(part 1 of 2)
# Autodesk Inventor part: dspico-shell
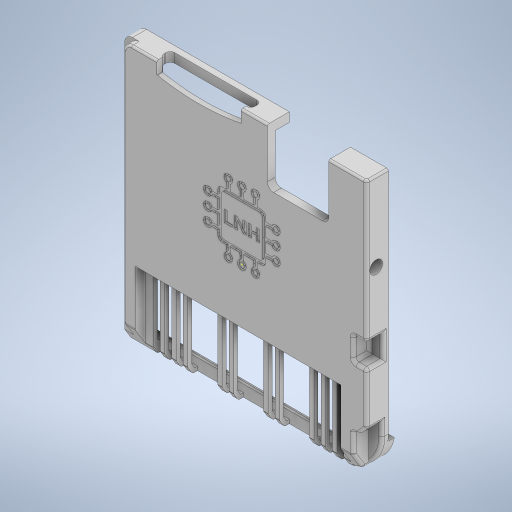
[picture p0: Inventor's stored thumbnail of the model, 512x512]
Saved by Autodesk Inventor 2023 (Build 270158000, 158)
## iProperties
RuleStatus: InUse
Created: 2023-10
Material: Genérico
Document SubType Name: Modeling
Density: 1 g/cm^3
Appearance: Valor por defecto
Author: RCuevas/Nitehack
Title: dspico-shell
Revision Number: v1.4
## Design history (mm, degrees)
sketch "Boceto1"
  geometry: L1 (16.3, -17.5)-(-16.3, -17.5); L2 (-16.3, -17.5)-(-16.3, 17.5); L3 (-16.3, 17.5)-(16.3, 17.5); L4 (16.3, 17.5)-(16.3, -17.5); L5 (16.3, -17.5)-(-16.3, 17.5); L6 (-16.3, -17.5)-(16.3, 17.5); 1 further point
  constraints: 12 end point, 2 midpoint, 2 parallel, 1 horizontal, 1 perpendicular
  dimensions: "d0" = 32.6 distance of L2.end L3.end; "d1" = 35 distance of L1.end L2.end
extrude "Extrusión1" new body sketch "Boceto1" stored distance "d2" = 3.85; taper "d3" = 0 deg
sketch "Boceto2"
  geometry: L1 (0, 35)-(3.85, 35) reference; L2 (0, 0)-(0, 35) reference; L3 (3.85, 0)-(0, 0) reference; L4 (3.85, 35)-(3.85, 0) reference; L5 (2.85, 0)-(2.85, 35); L6 (0, 35)-(0, 0) reference; L7 (0, 13.7)-(1.95, 13.7); L8 (1.95, 13.7)-(1.95, 16.7); L9 (1.95, 16.7)-(0, 16.7); L10 (2.85, 5)-(3.85, 5); L11 (3.85, 0)-(3.85, 35) reference; L12 (2.85, 5)-(2.85, 35); L13 (3.85, 35)-(0, 35) reference; L14 (2.85, 35)-(3.85, 35); 1 further point
  constraints: 14 end point, 6 point on line, 4 perpendicular, 1 collinear, 1 vertical
  dimensions: "d4" = 2.85 distance between parallel lines of L2 L5; "d5" = 3 distance of L7.end L8.end; "d6" = 1.95 distance of L7.start L7.end; "d7" = 18.3 distance between parallel lines of L1 L9; "d8" = 5 distance between parallel lines of L3 L10
extrude "Extrusión2" cut sketch "Boceto2" extent not by distance; stored distance "d9" = 0; taper "d10" = 0 deg
sketch "Boceto3"
  geometry: L1 (16.3, 17.5)-(-16.3, 17.5) reference; L2 (-16.3, 17.5)-(-16.3, -17.5) reference; L3 (-16.3, -17.5)-(16.3, -17.5) reference; L4 (16.3, -0.8)-(14.54, -0.8); L5 (14.54, -0.8)-(14.54, -3.8); L6 (14.54, -3.8)-(16.3, -3.8); L7 (16.3, -17.5)-(-16.3, -17.5) reference; L8 (14.54, -17.5)-(14.54, -11.4); L9 (14.54, -11.4)-(15.54, -11.4); L10 (15.54, -11.4)-(16.3, -10.5); L11 (-15.4, 17.5)-(-15.4, -17.5); 7 further points; 1 other entity
  constraints: 14 end point, 5 perpendicular, 3 point on line, 1 horizontal, 2 other
  dimensions: "d11" = 1.76 distance of L5.end L6.end; "d12" = 6.1 distance of L8.start L8.end; "d13" = 1.76 dimension on L8; "d14" = 1 distance of L8.end L9.end; "d15" = 7 distance from line of L3 L10.end; "d16" = 0.9 distance between parallel lines of L2 L11
  node "Contorno proyectado2"
extrude "Extrusión3" cut sketch "Boceto3" distance "d17" = 1; taper "d18" = 0 deg
extrude "Extrusión4" cut sketch "Boceto3" distance "d19" = 2.15; taper "d20" = 0 deg
extrude "Extrusión5" cut sketch "Boceto3" distance "d21" = 2; taper "d22" = 0 deg
fillet "Empalme1" dims "d23" = 5
sketch "Boceto5"
  geometry: L1 (-14.4, 1.925)-(-17.5, 0.025); L2 (-16.308, 1.925)-(-17.5, 1.925) reference; L3 (-17.5, 1.925)-(-17.5, -1.925) reference; L4 (-17.5, -1.925)-(-12.5, -1.925) reference; L5 (-12.5, -1.925)-(-12.5, -0.925) reference; L6 (-12.5, -0.925)-(-12.5, -0.075) reference; L7 (-12.5, -0.075)-(-16.308, -0.075) reference; L8 (-16.308, -0.075)-(-16.308, 1.925) reference; L9 (-16.308, -0.075)-(-16.308, 1.925) reference; L10 (-16.308, -0.075)-(-11.4, -0.075) reference; L11 (-11.4, 1.925)-(-11.4, -0.075) reference; L12 (-16.308, 1.925)-(-11.4, 1.925) reference; 2 further points
  constraints: 2 end point, 2 point on line, 1 other
  dimensions: "d24" = 3 distance from line of L1.start L11
extrude "Extrusión6" cut sketch "Boceto5" extent not by distance; stored distance "d25" = 0; taper "d26" = 0 deg
fillet "Empalme2" dims "d27" = 0.4
sketch "Boceto6"
  geometry: L1 (-13.9, -20)-(-13.9, -7.2); L2 (-13.9, -7.2)-(12.946, -7.2); L3 (12.946, -7.2)-(12.946, -19.174); L4 (11.3, -17.309)-(-16.3, -17.309) reference; L5 (0, 0)-(0, -20.377); L6 (-16.3, -17.5)-(11.3, -17.5) reference; L7 (16.3, -10.354)-(16.3, -4.2) reference; L8 (-16.3, -16.032)-(-16.3, 17.5) reference; A1 r 5 centre (11.3, -12.5) between (11.3, -17.5) and (14.387, -16.433) reference; 2 further points
  constraints: 8 end point, 2 perpendicular, 2 vertical
  dimensions: "d28" = 10.3 distance between parallel lines of L2 L6; "d29" = 3.354 distance between parallel lines of L3 L7; "d63" = 2.4 distance between parallel lines of L8 L1; "d64" = 26.846 distance of L1.end L2.end (derived)
extrude "Extrusión7" cut sketch "Boceto6" distance "d32" = 1.3; taper "d33" = 0 deg
sketch "Boceto7"
  geometry: L1 (12.946, -16.521)-(-13.9, -16.521) reference; L2 (12.946, -7.2)-(12.946, -16.521) reference; L3 (-13.9, -7.2)-(12.946, -7.2) reference; L4 (-13.9, -16.521)-(-13.9, -7.2) reference; L5 (12.946, -14.496)-(12.946, -16.521) reference; L6 (12.946, -16.521)-(-13.9, -16.521) reference; L7 (-13.9, -16.521)-(-13.9, -14.496) reference; L8 (-15.4, -14.496)-(-13.9, -14.496) reference; L9 (-16.3, -16.032)-(-15.4, -16.032) reference; L10 (11.3, -17.309)-(-16.3, -17.309) reference; L11 (14.14, -14.496)-(14.14, -16.328) reference; L12 (12.946, -14.496)-(14.14, -14.496) reference; L13 (-16.3, -17.5)-(11.3, -17.5) reference; L14 (11.3, -17.309)-(11.3, -17.5) reference; L15 (11.3, -17.309)-(-16.3, -17.309) reference; L16 (-13.9, -16.521)-(-13.9, -17.5); L17 (12.946, -16.521)-(12.946, -17.221); L18 (-16.3, -17.309)-(-16.3, -17.5) reference; L19 (-15.4, -16.032)-(-15.4, -14.496) reference; L20 (-16.3, -17.309)-(-16.3, -16.032) reference; A1 r 4.6 centre (11.3, -12.709) between (11.3, -17.309) and (14.14, -16.328) reference; A2 r 5 centre (11.3, -12.5) between (11.3, -17.5) and (14.387, -16.433) reference; A3 r 5 centre (11.3, -12.5) between (11.3, -17.5) and (16.3, -12.5) reference; A4 r 5 centre (11.3, -12.5) between (14.387, -16.433) and (16.3, -12.5) reference; 9 further points
  constraints: 4 end point, 2 point on line, 1 parallel, 1 point on circle
extrude "Extrusión8" cut sketch "Boceto7" distance "d34" = 1.25; taper "d35" = 0 deg
sketch "Boceto12"
  geometry: 1 further point
sketch "Boceto13"
  geometry: L1 (12.946, -7.2)-(12.946, -17.221) reference; L2 (-13.9, -7.2)-(12.946, -7.2) reference; L3 (-13.9, -17.5)-(-13.9, -7.2) reference; L4 (11.3, -17.5)-(-13.9, -17.5) reference; L5 (12.046, -17.5)-(12.046, -8.2); L6 (12.046, -8.2)-(-12.854, -8.2); L7 (-12.854, -8.2)-(-12.854, -17.5); L8 (-13.9, -14.287)-(-13.9, -14.496) reference; L9 (19, -16)-(-21.001, -16); A1 r 5 centre (11.3, -12.5) between (11.3, -17.5) and (12.946, -17.221) reference; 3 further points
  constraints: 8 end point, 3 perpendicular, 2 point on line, 1 midpoint, 1 vertical
  dimensions: "d40" = 0.9 distance between parallel lines of L5 L1; "d41" = 1.046 distance from line of point (-13.9, -14.392) L7; "d42" = 1 distance between parallel lines of L2 L6; "d43" = 1.5 distance between parallel lines of L4 L9
extrude "Extrusión10" join sketch "Boceto13" distance "d44" = 1.25; taper "d45" = 0 deg
sketch "Boceto14"
  geometry: L1 (-1.3, -1.474)-(-2.263, -2.892) reference; L2 (-2.263, -2.892)-(-2.059, -2.892) reference; L3 (-1.811, -2.761)-(-1, -1.566) reference; L4 (-1.3, -1.474)-(-1, -1.566) reference; L5 (-2.124, -3.213)-(-1.3, -3.213) reference; L6 (-1.3, -2.234)-(-1.3, -3.213) reference; L7 (-1.783, -3.022)-(-1.3, -2.234) reference; A1 r 0.3 centre (-2.059, -2.592) between (-2.059, -2.892) and (-1.811, -2.761) reference; A2 r 0.4 centre (-2.124, -2.813) between (-2.124, -3.213) and (-1.783, -3.022) reference; 3 further points
extrude "Extrusión11" cut sketch "Boceto14" extent not by distance; stored distance "d46" = 0; taper "d47" = 0 deg
fillet "Empalme3" dims "d48" = 0.1
sketch "Boceto15"
  geometry: L1 (-12.854, -8.2)-(-12.854, -17.4) reference; L2 (11.3, -17.5)-(-12.954, -17.5) reference; L3 (12.046, -17.326)-(12.046, -8.2) reference; L4 (12.046, -8.2)-(-12.854, -8.2) reference; L5 (-19, -16)-(20, -16); A1 r 0.1 centre (-12.954, -17.4) between (-12.954, -17.5) and (-12.854, -17.4) reference; A2 r 5 centre (11.3, -12.5) between (11.3, -17.5) and (12.163, -17.425) reference; A3 r 0.1 centre (12.146, -17.326) between (12.046, -17.326) and (12.163, -17.425) reference; 3 further points
  constraints: 2 end point
  dimensions: "d50" = 1.5 distance between parallel lines of L2 L5
extrude "Extrusión12" cut sketch "Boceto15" extent not by distance; stored distance "d51" = 0; taper "d52" = 0 deg
node "Plano de trabajo1"
sketch "Boceto16"
  geometry: L1 (-0.3, -4.9)-(-0.726, -4.9) reference; L2 (-0.3, -3.5)-(-0.3, -4.9) reference; L3 (-0.3, -3.5)-(1, -3.5) reference; L4 (1, 0)-(1, -3.5) reference; L5 (0, 0)-(1, 0) reference; L6 (0, 4.3)-(0, 0) reference; L7 (-1.55, 4.3)-(0, 4.3) reference; L8 (-1.55, -3.83)-(-1.55, 4.3) reference; L9 (-1.535, -4.045)-(-1.067, -4.809) reference; L10 (-1.535, -4.045)-(-1.067, -4.809) reference; L11 (-1.067, -4.809)-(-0.982, -4.757) reference; L12 (-0.982, -4.757)-(-1.55, -3.83) reference; L13 (-1.55, -3.83)-(-1.55, -3.993) reference; L14 (-0.726, -5)-(-0.726, -4.9) reference; L15 (-1.067, -4.809)-(-0.982, -4.757) reference; L16 (-0.3, -5)-(-0.3, -4.9) reference; L17 (-0.3, -4.9)-(-0.726, -4.9) reference; L18 (-0.726, -5)-(-0.3, -5) reference; L19 (-1.05, 4.3)-(-1.05, -3.88); L20 (-1.05, -3.88)-(-0.67, -4.5); L21 (-0.67, -4.5)-(-0.3, -4.5); L22 (-0.726, -5)-(-0.726, -4.9) reference; L23 (-0.982, -4.757)-(-1.55, -3.83) reference; A1 r 0.1 centre (-1.45, -3.993) between (-1.55, -3.993) and (-1.535, -4.045) reference; A2 r 0.3 centre (-0.726, -4.6) between (-0.982, -4.757) and (-0.726, -4.9) reference; A3 r 0.4 centre (-0.726, -4.6) between (-1.067, -4.809) and (-0.726, -5) reference; A4 r 0.3 centre (-0.726, -4.6) between (-0.982, -4.757) and (-0.726, -4.9) reference; 8 further points
  constraints: 6 end point, 3 parallel, 2 midpoint, 2 perpendicular, 2 point on line, 1 vertical
  dimensions: "d54" = 0.5 distance between parallel lines of L19 L8; "d56" = 0.5 distance from line of point (-0.86, -4.19) L9; "d57" = 0.5 distance from line of point (-0.513, -5) L21
extrude "Extrusión13" join sketch "Boceto16" distance "d58" = 0.6; taper "d59" = 0 deg
pattern_linear "Patrón rectangular1" dims "d62" = 1.5
fillet "Empalme5" dims "d65" = 1
sketch "Boceto19"
  geometry: L1 (-15.4, 16.5)-(-15.4, -14.287) reference; L2 (-13.9, -14.287)-(-15.4, -14.287) reference; L3 (-13.9, -14.287)-(-13.9, -7.2) reference; L4 (-13.9, -7.2)-(12.946, -7.2) reference; L5 (12.946, -7.2)-(12.946, -14.287) reference; L6 (14.14, -14.287)-(12.946, -14.287) reference; L7 (14.14, -11.8)-(14.14, -14.287) reference; L8 (14.833, -11.4)-(15.016, -11.4) reference; L9 (15.9, -10.354)-(15.016, -11.4) reference; L10 (15.9, -4.2)-(15.9, -10.354) reference; L11 (14.94, -4.2)-(15.9, -4.2) reference; L12 (15.9, -0.4)-(14.94, -0.4) reference; L13 (15.9, 17.5)-(15.9, -0.4) reference; L14 (15.9, 17.5)-(-14.4, 17.5) reference; L15 (16.3, 17.5)-(-15.3, 17.5) reference; L16 (3.35, 17.5)-(11.35, 17.5); L17 (11.35, 17.5)-(11.35, 10.2); L18 (11.35, 10.2)-(3.35, 10.2); L19 (3.35, 10.2)-(3.35, 17.5); L20 (16.3, -0.4)-(16.3, 17.5) reference; L21 (14.14, -1.2)-(14.14, -3.4) reference; A1 r 1 centre (-14.4, 16.5) between (-14.4, 17.5) and (-15.4, 16.5) reference; A2 r 0.8 centre (14.94, -3.4) between (14.14, -3.4) and (14.94, -4.2) reference; A3 r 0.8 centre (14.94, -1.2) between (14.94, -0.4) and (14.14, -1.2) reference; 4 further points
  constraints: 8 end point, 2 parallel, 1 horizontal, 1 midpoint, 1 perpendicular, 1 point on line, 1 other
  dimensions: "d67" = 7.3 distance of L18.end L16.start; "d68" = 8 distance of L17.end L18.end; "d311" = 8.95 distance from line of point (7.35, 10.2) L20
extrude "Extrusión14" cut sketch "Boceto19" extent not by distance; stored distance "d70" = 0; taper "d71" = 0 deg
node "Plano de trabajo2"
sketch "Boceto20" dims "d76" = 2
  geometry: L1 (12.95, 30)-(12.95, 22.7) reference; L2 (12.95, 22.7)-(4.95, 22.7) reference; L3 (4.95, 22.7)-(4.95, 30) reference; L4 (0, 30)-(4.95, 30) reference; L5 (0, 0)-(0, 30) reference; L6 (0, 0)-(4.254, 0) reference; L7 (4.254, 0)-(4.254, 4.3) reference; L8 (4.254, 4.3)-(29.154, 4.3) reference; L9 (29.154, 4.3)-(29.154, 0) reference; L10 (29.154, 0)-(32.6, 0) reference; L11 (32.6, 29)-(32.6, 0) reference; L12 (12.95, 30)-(31.6, 30) reference; L13 (3.75, 21.5)-(14.15, 21.5); L14 (14.15, 21.5)-(14.15, 28.8); L15 (14.15, 28.8)-(31.4, 28.8); L16 (31.4, 28.8)-(31.4, 1.2); L17 (31.4, 1.2)-(30.354, 1.2); L18 (30.354, 1.2)-(30.354, 5.7); L19 (30.354, 5.7)-(3.054, 5.7); L20 (3.054, 5.7)-(3.054, 1.2); L21 (3.054, 1.2)-(1.2, 1.2); L22 (1.2, 1.2)-(1.2, 28.8); L23 (1.2, 28.8)-(3.75, 28.8); L24 (3.75, 28.8)-(3.75, 21.5); L25 (3.09, 8.93)-(29.511, 8.93); L26 (16.3, 8.93)-(16.3, 15); L27 (5, -5)-(32.6, -5) reference; L28 (1.2, 9.33)-(2.173, 9.33); L29 (2.173, 9.33)-(2.173, 8.53); L30 (2.173, 8.53)-(1.2, 8.53); L31 (1.2, 8.53)-(1.2, 9.33); L32 (30.427, 9.33)-(31.4, 9.33); L33 (31.4, 9.33)-(31.4, 8.53); L34 (31.4, 8.53)-(30.427, 8.53); L35 (30.427, 8.53)-(30.427, 9.33); L36 (31.4, 1.2)-(31.4, -3.5); L37 (31.4, -3.5)-(-0.287, -3.5); L38 (29.154, -3.5)-(4.254, -3.5) reference; L39 (32.6, -5)-(32.6, 0) reference; L40 (3.75, 28.8)-(4.95, 28.8); L41 (12.95, 28.8)-(14.15, 28.8); L42 (1.2, 12.6)-(2.4, 12.6); L43 (2.4, 12.6)-(2.4, 8.4); L44 (2.4, 8.4)-(1.2, 8.4); C1 r 0.6 at (29.511, 8.93); C2 r 0.6 at (3.09, 8.93); C3 r 1 at (31.6, 29); C4 r 0.6 at (31.6, 29); C5 r 1 at (1, 29); C6 r 0.6 at (1, 29); A1 r 1 centre (31.6, 29) between (32.6, 29) and (31.6, 30) reference; 17 further points
  constraints: 58 end point, 6 centre point, 6 horizontal, 6 perpendicular, 6 point on line, 5 coincident, 4 midpoint, 4 parallel, 2 collinear, 2 horizontal alignment, 2 vertical, 1 equal radius, 1 vertical alignment, 15 other
  dimensions: "d72" = 1.2 distance between parallel lines of L22 L5; "d73" = 1.2 diameter of C2; "d74" = 26.421 distance of L25.start L25.end; "d75" = 13.93 distance between parallel lines of L25 L27; "d77" = 0.8 distance of L28.end L29.end; "d82" = 2.4 distance between parallel lines of L5 L43; "d83" = 4.2 distance of L42.end L43.end; "d84" = 13.4 distance from line of L27 point (1.8, 8.4); "d308" = 4.5 distance of L19.end L20.end; "d318" = 2 diameter of C3; "d319" = 1.2 diameter of C4; "d322" = 2 diameter of C5; "d323" = 1.2 diameter of C6; "d331" = 1.2 distance between parallel lines of L11 L16
  node "Contorno proyectado21"
extrude "Extrusión15" cut sketch "Boceto20" distance "d80" = 1.85; taper "d81" = 0 deg
extrude "Extrusión16" cut sketch "Boceto20" distance "d85" = 1.65; taper "d86" = 0 deg
sketch "Boceto23"
  geometry: L1 (29.154, 0)-(29.154, -3.5) reference; L2 (29.154, -3.5)-(4.254, -3.5) reference; L3 (4.254, -3.5)-(4.254, 0) reference; L4 (4.254, 0)-(0, 0) reference; L5 (5, -5)-(32.6, -5) reference; L6 (32.6, -5)-(32.6, 0) reference; L7 (32.6, 0)-(29.154, 0) reference; L8 (12.95, 28.8)-(30.62, 28.8) reference; L9 (31.4, 28.02)-(31.4, 9.33) reference; L10 (31.4, 1.2)-(30.354, 1.2) reference; L11 (30.354, 1.2)-(30.354, 5.7) reference; L12 (30.354, 5.7)-(3.054, 5.7) reference; L13 (3.054, 5.7)-(3.054, 1.2) reference; L14 (3.054, 1.2)-(1.2, 1.2) reference; L15 (1.2, 1.2)-(1.2, 8.4) reference; L16 (1.98, 28.8)-(4.95, 28.8) reference; L17 (4.95, 28.8)-(4.95, 30) reference; L18 (0, 30)-(4.95, 30) reference; L19 (0, 0)-(0, 30) reference; L20 (0, 0)-(4.254, 0) reference; L21 (4.254, 0)-(4.254, 4.3) reference; L22 (4.254, 4.3)-(29.154, 4.3) reference; L23 (29.154, 4.3)-(29.154, 0) reference; L24 (29.154, 0)-(32.6, 0) reference; L25 (32.6, 29)-(32.6, 0) reference; L26 (12.95, 30)-(31.6, 30) reference; L27 (12.95, 30)-(12.95, 28.8) reference; L28 (0.938, -0.85)-(3.404, -0.85); L29 (3.404, -0.85)-(3.404, -4.35); L30 (3.404, -4.35)-(30.004, -4.35); L31 (30.004, -4.35)-(30.004, -0.85); L32 (30.004, -0.85)-(31.75, -0.85); L33 (31.75, -4.15)-(5, -4.15); L34 (34, -2)-(31.199, -2); L35 (0.938, -0.85)-(-0.172, -0.85); L36 (31.4, 9.33)-(30.427, 9.33) reference; L37 (30.427, 8.53)-(31.4, 8.53) reference; L38 (31.4, 8.53)-(31.4, 1.2) reference; L39 (1.2, 8.4)-(2.242, 8.4) reference; L40 (2.4, 9.654)-(2.4, 12.6) reference; L41 (2.4, 12.6)-(1.2, 12.6) reference; L42 (1.2, 12.6)-(1.2, 28.02) reference; C1 r 0.6 at (29.511, 8.93) reference; A1 r 5 centre (5, 0) between (0, 0) and (5, -5) reference; A2 r 1 centre (29.511, 8.93) between (30.427, 9.33) and (30.427, 8.53) reference; A3 r 1 centre (31.6, 29) between (32.6, 29) and (31.6, 30) reference; A4 r 4.15 centre (5, 0) between (0.938, -0.85) and (5, -4.15); A5 r 1 centre (3.09, 8.93) between (2.242, 8.4) and (2.4, 9.654) reference; A6 r 1 centre (31.6, 29) between (30.62, 28.8) and (31.4, 28.02) reference; A7 r 1 centre (1, 29) between (1.2, 28.02) and (1.98, 28.8) reference; 6 further points; 1 other entity
  constraints: 16 end point, 2 horizontal, 2 point on circle, 1 centre point, 11 other
  dimensions: "d89" = 0.85 distance between parallel lines of L4 L28; "d90" = 3 distance between parallel lines of L5 L34
extrude "Extrusión17" cut sketch "Boceto23" extent not by distance; stored distance "d91" = 0; taper "d92" = 0 deg
sketch "Boceto25"
  geometry: L1 (32.6, 29)-(32.6, -2) reference; L2 (12.95, 30)-(31.6, 30) reference; L3 (12.95, 30)-(12.95, 28.8) reference; L4 (12.95, 28.8)-(30.62, 28.8) reference; L5 (31.4, 28.02)-(31.4, 9.33) reference; L6 (31.4, 1.2)-(30.354, 1.2) reference; L7 (30.354, 1.2)-(30.354, 5.7) reference; L8 (30.354, 5.7)-(3.054, 5.7) reference; L9 (3.054, 5.7)-(3.054, 1.2) reference; L10 (3.054, 1.2)-(1.2, 1.2) reference; L11 (1.2, 1.2)-(1.2, 8.4) reference; L12 (1.98, 28.8)-(4.95, 28.8) reference; L13 (4.95, 28.8)-(4.95, 30) reference; L14 (0, 30)-(4.95, 30) reference; L15 (0, 0)-(0, 30) reference; L16 (0.073, -0.85)-(0.938, -0.85) reference; L17 (5, -4.15)-(31.75, -4.15) reference; L18 (31.75, -4.15)-(31.75, -2) reference; L19 (31.75, -2)-(32.6, -2) reference; L20 (29.154, -3.5)-(29.154, 4.3) reference; L21 (4.254, -3.5)-(29.154, -3.5) reference; L22 (4.254, -3.5)-(4.254, 4.3) reference; L23 (4.254, 4.3)-(29.154, 4.3) reference; L24 (30.354, 1.2)-(30.354, -3.5); L25 (30.354, -3.5)-(31.4, -3.5); L26 (31.4, -3.5)-(31.4, 1.2); L27 (3.054, 1.2)-(3.054, -3.665); L28 (2.383, -3.221)-(2.383, 1.2); L29 (3.054, 1.2)-(1.2, 1.2) reference; L30 (3.054, 1.2)-(2.383, 1.2); L31 (31.75, -4.15)-(5, -4.15) reference; L32 (30.354, -4.15)-(30.354, -3.5); L33 (4.254, -3.83)-(4.254, -4.757) reference; L34 (4.254, -3.5)-(4.254, -3.83); L35 (4.254, -3.5)-(29.154, -3.5) reference; L36 (29.154, -3.5)-(30.354, -3.5); L37 (4.254, -3.5)-(3.054, -3.5); L38 (3.054, 5.7)-(2.7, 5.7); L39 (2.7, 5.7)-(2.7, -3.454); L40 (31.4, 9.33)-(30.427, 9.33) reference; L41 (30.427, 8.53)-(31.4, 8.53) reference; L42 (31.4, 8.53)-(31.4, 1.2) reference; L43 (1.2, 8.4)-(2.242, 8.4) reference; L44 (2.4, 9.654)-(2.4, 12.6) reference; L45 (2.4, 12.6)-(1.2, 12.6) reference; L46 (1.2, 12.6)-(1.2, 28.02) reference; C1 r 0.6 at (29.511, 8.93) reference; A1 r 1 centre (31.6, 29) between (32.6, 29) and (31.6, 30) reference; A2 r 1 centre (29.511, 8.93) between (30.427, 9.33) and (30.427, 8.53) reference; A3 r 5 centre (5, 0) between (0, 0) and (0.073, -0.85) reference; A4 r 4.15 centre (5, 0) between (0.938, -0.85) and (5, -4.15) reference; A5 r 1 centre (3.09, 8.93) between (2.242, 8.4) and (2.4, 9.654) reference; A6 r 1 centre (31.6, 29) between (30.62, 28.8) and (31.4, 28.02) reference; A7 r 1 centre (1, 29) between (1.2, 28.02) and (1.98, 28.8) reference; 2 further points
  constraints: 24 end point, 7 perpendicular, 3 point on circle, 3 point on line, 2 vertical, 1 horizontal
  dimensions: "d93" = 0.65 distance from line of L17 L24.end; "d119" = 1.5 distance between parallel lines of L11 L39
extrude "Extrusión18" cut sketch "Boceto25" distance "d94" = 1; taper "d95" = 0 deg
fillet "Empalme9" dims "d96" = 0.25
fillet "Empalme10" dims "d97" = 0.25
sketch "Boceto26"
  geometry: L1 (18.65, -1)-(18.65, 1.85) reference; L2 (18.65, 1.85)-(0, 1.85) reference; L3 (0, 0)-(0, 1.85) reference; L4 (0, 0)-(0.9, 0) reference; L5 (0.9, -1)-(0.9, 0) reference; L6 (18.65, -1)-(0.9, -1) reference; L7 (4.5, 0.95)-(15.19, 0.95); L8 (15.69, 0.45)-(15.69, 0.25); L9 (15.19, -0.25)-(4.5, -0.25); L10 (4, 0.25)-(4, 0.45); L11 (4, 0.95)-(15.69, -0.25); L12 (15.69, 0.95)-(4, -0.25); L13 (15.19, 1.05)-(4.5, 1.05); L14 (3.9, 0.45)-(3.9, 0.25); L15 (4.5, -0.35)-(15.19, -0.35); L16 (15.79, 0.25)-(15.79, 0.45); A1 r 0.5 centre (15.19, 0.25) between (15.19, -0.25) and (15.69, 0.25); A2 r 0.5 centre (15.19, 0.45) between (15.69, 0.45) and (15.19, 0.95); A3 r 0.5 centre (4.5, 0.45) between (4.5, 0.95) and (4, 0.45); A4 r 0.5 centre (4.5, 0.25) between (4, 0.25) and (4.5, -0.25); A5 r 0.6 centre (4.5, 0.45) between (4.5, 1.05) and (3.9, 0.45); A6 r 0.6 centre (4.5, 0.25) between (3.9, 0.25) and (4.5, -0.35); A7 r 0.6 centre (15.19, 0.25) between (15.19, -0.35) and (15.79, 0.25); A8 r 0.6 centre (15.19, 0.45) between (15.79, 0.45) and (15.19, 1.05); 2 further points
  constraints: 20 end point, 16 point on circle, 8 centre point, 8 point on line, 8 tangent, 4 parallel, 2 midpoint, 2 perpendicular, 1 equal radius, 1 horizontal, 7 other
  dimensions: "d98" = 1.2 distance of L12.end L11.start; "d99" = 11.69 distance of L11.end L12.end; "d100" = 1.5 distance from line of point (9.845, 0.35) L2; "d104" = 0.5 radius of A1; "d105" = 0.5 radius of A2; "d106" = 0.5 radius of A3; "d203" = 0.1 distance between parallel lines of L7 L13; "d312" = 4 distance between parallel lines of L3 L10
extrude "Extrusión19" cut sketch "Boceto26" distance "d102" = 10; taper "d103" = 0 deg
node "Plano de trabajo3"
sketch "Boceto27"
  geometry: L1 (-14.054, -11.55)-(-14.054, -15.75) reference; L2 (-13.804, -16)-(12.996, -16) reference; L3 (14.134, 16.3)-(11.35, 16.3) reference; L4 (11.35, 16.3)-(11.35, 17.5) reference; L5 (16.3, 17.5)-(11.35, 17.5) reference; L6 (16.3, -12.5)-(16.3, 17.5) reference; L7 (16.227, -13.35)-(15.362, -13.35) reference; L8 (11.3, -16.65)-(-15.45, -16.65) reference; L9 (-15.45, -16.65)-(-15.45, -14.5) reference; L10 (-15.45, -14.5)-(-16.3, -14.5) reference; L11 (-16.3, 16.5)-(-16.3, -14.5) reference; L12 (3.35, 17.5)-(-15.3, 17.5) reference; L13 (3.35, 17.5)-(3.35, 16.3) reference; L14 (3.35, 16.3)-(-14.134, 16.3) reference; L15 (-15.1, 15.334)-(-15.1, -2.92) reference; L16 (-14.85, -11.3)-(-14.304, -11.3) reference; L17 (3.35, 16.3)-(11.35, 16.3); L18 (3.35, 17.5)-(-14.4, 17.5) reference; L19 (11.35, 17.5)-(11.35, 10.2) reference; L20 (3.35, 10.2)-(3.35, 17.5) reference; L21 (11.35, 17.5)-(3.35, 17.5); L22 (13.6, -15.954)-(13.6, -11.3) reference; L23 (14.15, 0.1)-(14.85, 0.1) reference; L24 (15.1, 0.35)-(15.1, 15.334) reference; L25 (14.85, -4.1)-(14.058, -4.1) reference; L26 (13.9, -2.4)-(13.9, -0.15) reference; L27 (-14.85, -3.17)-(-14.278, -3.17) reference; L28 (-14.278, -3.97)-(-14.85, -3.97) reference; L29 (-15.1, -4.22)-(-15.1, -11.05) reference; L30 (12.996, -16.288)-(12.996, -16) reference; L31 (13.6, -11.3)-(15.1, -11.3) reference; L32 (15.1, -11.3)-(15.1, -4.35) reference; C1 r 0.6 at (-13.211, -3.57) reference; A1 r 5 centre (11.3, -12.5) between (16.227, -13.35) and (16.3, -12.5) reference; A2 r 1 centre (-15.3, 16.5) between (-15.3, 17.5) and (-16.3, 16.5) reference; A3 r 1 centre (-13.211, -3.57) between (-14.065, -4.09) and (-14.065, -3.05) reference; A4 r 4.15 centre (11.3, -12.5) between (13.6, -15.954) and (15.362, -13.35) reference; A5 r 4.15 centre (11.3, -12.5) between (11.3, -16.65) and (12.996, -16.288) reference; A6 r 4.15 centre (11.3, -12.5) between (9.07, -16) and (15.276, -11.311); A7 r 3.798 centre (11.3, -12.5) between (9.825, -16) and (14.973, -11.535); A8 r 1 centre (13.21, -3.57) between (13.562, -2.634) and (14.058, -4.1) reference; A9 r 1 centre (-15.3, 16.5) between (-14.94, 15.567) and (-14.367, 16.14) reference; A10 r 1 centre (15.3, 16.5) between (14.367, 16.14) and (14.94, 15.567) reference; A11 r 0.25 centre (-14.134, 16.05) between (-14.134, 16.3) and (-14.367, 16.14) reference; A12 r 0.25 centre (-14.85, 15.334) between (-14.94, 15.567) and (-15.1, 15.334) reference; A13 r 0.25 centre (14.85, 15.334) between (15.1, 15.334) and (14.94, 15.567) reference; A14 r 0.25 centre (14.134, 16.05) between (14.367, 16.14) and (14.134, 16.3) reference; A15 r 0.25 centre (14.15, -0.15) between (14.15, 0.1) and (13.9, -0.15) reference; A16 r 0.25 centre (14.85, 0.35) between (14.85, 0.1) and (15.1, 0.35) reference; A17 r 0.25 centre (13.65, -2.4) between (13.562, -2.634) and (13.9, -2.4) reference; A18 r 0.25 centre (-14.304, -11.55) between (-14.054, -11.55) and (-14.304, -11.3) reference; A19 r 0.25 centre (-13.804, -15.75) between (-14.054, -15.75) and (-13.804, -16) reference; A20 r 0.25 centre (-14.85, -2.92) between (-15.1, -2.92) and (-14.85, -3.17) reference; A21 r 0.25 centre (-14.278, -2.92) between (-14.278, -3.17) and (-14.065, -3.05) reference; A22 r 0.25 centre (-14.278, -4.22) between (-14.065, -4.09) and (-14.278, -3.97) reference; A23 r 0.25 centre (-14.85, -4.22) between (-14.85, -3.97) and (-15.1, -4.22) reference; A24 r 0.25 centre (-14.85, -11.05) between (-15.1, -11.05) and (-14.85, -11.3) reference; A25 r 0.25 centre (14.85, -4.35) between (15.1, -4.35) and (14.85, -4.1) reference; 11 further points
  constraints: 6 point on circle, 4 end point, 2 centre point, 2 coincident, 2 point on line, 1 parallel
extrude "Extrusión20" new body sketch "Boceto27" distance "d108" = 0.6; taper "d109" = 0 deg
fillet "Empalme11" dims "d110" = 0.25
feature "Engrosado1" dims "d111" = 0.1, "d112" = 0.05
feature "Engrosado2" dims "d115" = 0.2, "d116" = 0.1
feature "Engrosado3" dims "d117" = 0.15, "d118" = 0.25
fillet "Empalme13" dims "d121" = 0.8
fillet "Empalme14" dims "d122" = 0.25
sketch "Boceto30"
  geometry: 1 further point
feature "Open CASCADE STEP translator 6.8 1.1.1.1_1:1"
feature "R0402_4:1"
feature "R0402_6:1"
feature "COMPOUND_(1)_8:1"
feature "COMPOUND_(1)_8:2"
feature "COMPOUND_(1)_8:3"
feature "COMPOUND_(1)_8:4"
feature "COMPOUND_(1)_8:5"
feature "COMPOUND_(1)_8:6"
feature "COMPOUND_(1)_15:1"
feature "COMPOUND_(1)_15:2"
feature "COMPOUND_(1)_15:3"
feature "COMPOUND_(1)_15:4"
feature "COMPOUND_(1)_15:5"
feature "COMPOUND_(1)_15:6"
feature "COMPOUND_(1)_15:7"
feature "COMPOUND_(1)_15:8"
feature "COMPOUND_(1)_15:9"
feature "COMPOUND_(1)_15:10"
feature "COMPOUND_(1)_15:11"
feature "COMPOUND_(1)_15:12"
feature "COMPOUND_(1)_15:13"
feature "COMPOUND_(1)_15:14"
feature "COMPOUND_(1)_15:15"
feature "COMPOUND_(1)_15:16"
feature "COMPOUND_(1)_15:17"
feature "COMPOUND_(1)_15:18"
feature "COMPOUND_(1)_15:19"
feature "COMPOUND_(1)_15:20"
feature "COMPOUND_(1)_15:21"
feature "COMPOUND_(1)_15:22"
feature "COMPOUND_(1)_15:23"
feature "COMPOUND_(1)_15:24"
feature "COMPOUND_(1)_15:25"
feature "COMPOUND_(1)_15:26"
feature "COMPOUND_(1)_15:27"
feature "COMPOUND_(1)_15:28"
feature "COMPOUND_(1)_15:29"
feature "COMPOUND_(1)_15:30"
feature "COMPOUND_(1)_15:31"
feature "COMPOUND_(1)_15:32"
feature "COMPOUND_(1)_15:33"
feature "COMPOUND_(1)_15:34"
feature "R0402_22:1"
feature "R0402_24:1"
feature "COMPOUND_(1)_15:35"
feature "COMPOUND_(1)_15:36"
feature "COMPOUND_(1)_15:37"
feature "COMPOUND_(1)_15:38"
feature "COMPOUND_(1)_15:39"
feature "COMPOUND_(1)_15:40"
feature "COMPOUND_(1)_15:41"
feature "COMPOUND_(1)_15:42"
feature "COMPOUND_(1)_15:43"
feature "COMPOUND_(1)_15:44"
feature "COMPOUND_(1)_15:45"
feature "COMPOUND_(1)_15:46"
feature "COMPOUND_(1)_15:47"
feature "COMPOUND_(1)_15:48"
feature "COMPOUND_(1)_15:49"
feature "COMPOUND_(1)_15:50"
feature "COMPOUND_(1)_15:51"
feature "ap2112k-3_3trg1_28:1"
feature "R0402_30:1"
feature "CAPC1005X56N_EIA_0402_32:1"
feature "CAPC1005X56N_EIA_0402_34:1"
feature "CAPC1005X56N_EIA_0402_36:1"
feature "CAPC1005X56N_EIA_0402_38:1"
feature "CAPC1005X56N_EIA_0402_40:1"
feature "CAPC1005X56N_EIA_0402_42:1"
feature "R0402_44:1"
feature "R0402_46:1"
feature "R0402_48:1"
feature "CAPC1005X56N_EIA_0402_50:1"
feature "CAPC1005X56N_EIA_0402_52:1"
feature "CAPC1005X56N_EIA_0402_54:1"
feature "CAPC1005X56N_EIA_0402_56:1"
feature "CAPC1005X56N_EIA_0402_58:1"
feature "CAPC1005X56N_EIA_0402_60:1"
feature "CAPC1005X56N_EIA_0402_62:1"
feature "CAPC1005X56N_EIA_0402_64:1"
feature "CAPC1005X56N_EIA_0402_66:1"
feature "COMPOUND_(1)_68:1"
feature "COMPOUND_(1)_68:2"
feature "COMPOUND_(1)_68:3"
feature "COMPOUND_(1)_68:4"
feature "COMPOUND_(1)_68:5"
feature "COMPOUND_(1)_73:1"
feature "COMPOUND_(1)_73:2"
feature "6833863024_78:1"
feature "6833863024_78:2"
feature "6833863024_78:3"
feature "6833863024_78:4"
feature "6833863024_78:5"
feature "6833863024_78:6"
feature "6833863024_78:7"
feature "6833863024_78:8"
feature "6833863024_78:9"
feature "6833863024_78:10"
feature "6833863024_78:11"
feature "6833862864_80:1"
feature "6833862864_80:2"
feature "6833862864_80:3"
feature "6833862864_80:4"
feature "6833862864_80:5"
feature "6833862864_80:6"
feature "6833862864_80:7"
feature "6833862864_80:8"
feature "6833862864_80:9"
feature "6833862864_80:10"
feature "6833862864_80:11"
feature "6833862864_80:12"
feature "6833862864_80:13"
feature "6833862864_80:14"
feature "6833862864_80:15"
feature "6833862864_80:16"
feature "6833862864_80:17"
feature "6833862864_80:18"
feature "6833862864_80:19"
feature "6833862864_80:20"
feature "6833862864_80:21"
feature "6833862864_80:22"
feature "6833862864_80:23"
feature "6833862864_80:24"
feature "6833862864_80:25"
feature "6833862864_80:26"
feature "6833862864_80:27"
feature "6833862864_80:28"
feature "6833862864_80:29"
feature "6833862864_80:30"
feature "6833862864_80:31"
feature "6833862864_80:32"
feature "6833862864_80:33"
feature "6833862864_80:34"
feature "6833862864_80:35"
feature "6833862864_80:36"
feature "6833862864_80:37"
feature "6833862864_80:38"
feature "6833862864_80:39"
feature "6833862864_80:40"
feature "6833862864_80:41"
feature "6833862864_80:42"
feature "6833862864_80:43"
feature "6833862864_80:44"
feature "6833862864_80:45"
feature "6833862864_80:46"
feature "6833862864_80:47"
feature "6833862864_80:48"
feature "6833862864_80:49"
feature "6833862864_80:50"
feature "6833862864_80:51"
feature "6833862864_80:52"
feature "6833862864_80:53"
feature "6833862864_80:54"
feature "6833862864_80:55"
feature "6833862864_80:56"
feature "6833862864_80:57"
feature "6833862864_80:58"
feature "6833862864_80:59"
feature "6833862864_80:60"
feature "6833862864_80:61"
feature "6833862864_80:62"
feature "6833862864_80:63"
feature "6833862864_80:64"
feature "6833862864_80:65"
feature "6833862864_80:66"
feature "6833862864_80:67"
feature "R0402_82:1"
feature "COMPOUND_(1)_84:1"
feature "COMPOUND_(1)_84:2"
feature "COMPOUND_(1)_84:3"
feature "COMPOUND_(1)_84:4"
feature "COMPOUND_(1)_84:5"
feature "COMPOUND_(1)_84:6"
feature "COMPOUND_(1)_84:7"
feature "R0402_89:1"
feature "R0402_91:1"
feature "R0402_93:1"
feature "R0402_95:1"
feature "R0402_97:1"
feature "5033981892_99:1"
feature "5033981892_101:1"
feature "Micro_SD_Card_102:1"
feature "Combinar1"
feature "Desplazar cuerpo1"
feature "Desplazar cuerpo2"
feature "Desplazar cuerpo3"
feature "Desplazar cuerpo4"
feature "Desplazar cuerpo5"
feature "Desplazar cuerpo6"
feature "Desplazar cuerpo7"
sketch "Boceto31"
  geometry: L1 (1.781, 17.657)-(1.781, 21.757); L2 (1.781, 21.757)-(4.881, 21.757); L3 (4.881, 21.757)-(4.881, 17.657); L4 (4.881, 17.657)-(1.781, 17.657); L5 (0.25, 30)-(4.95, 30) reference; L6 (0, 0)-(0, 29.75) reference; L7 (4.981, 17.557)-(4.981, 21.857); L8 (4.981, 21.857)-(1.681, 21.857); L9 (1.681, 21.857)-(1.681, 17.557); L10 (1.681, 17.557)-(4.981, 17.557); 1 further point
  constraints: 16 end point, 6 perpendicular, 3 other
  dimensions: "d226" = 8.24294 distance from line of L5 L2.end; "d227" = 3.1 distance of L1.end L2.end; "d228" = 4.1 distance of L2.end L3.end; "d229" = 1.78106 distance between parallel lines of L6 L1; "d231" = 0.1 distance between parallel lines of L3 L7
extrude "Extrusión22" cut sketch "Boceto31" distance "d145" = 0.7; taper "d146" = 0 deg
sketch "Boceto32"
  geometry: L1 (12.831, 10.957)-(12.831, 18.157); L2 (12.831, 18.157)-(5.631, 18.157); L3 (5.631, 18.157)-(5.631, 10.957); L4 (5.631, 10.957)-(12.831, 10.957); L5 (0.25, 30)-(4.95, 30) reference; L6 (5.531, 10.857)-(5.531, 18.257); L7 (5.531, 18.257)-(12.931, 18.257); L8 (12.931, 18.257)-(12.931, 10.857); L9 (12.931, 10.857)-(5.531, 10.857); 1 further point
  constraints: 16 end point, 4 perpendicular, 3 other
  dimensions: "d232" = 11.843 distance between parallel lines of L5 L2; "d233" = 7.2 distance of L1.start L1.end; "d234" = 7.2 distance of L3.end L1.start; "d235" = 0.1 distance between parallel lines of L3 L6
extrude "Extrusión23" cut sketch "Boceto32" distance "d148" = 0.4; taper "d149" = 0 deg
sketch "Boceto33"
  geometry: L1 (19.175, 7.928)-(19.175, 6.427); L2 (19.175, 6.427)-(16.082, 6.427); L3 (16.082, 6.427)-(16.082, 7.928); L4 (16.082, 7.928)-(19.175, 7.928); L5 (20.361, 8.846)-(21.862, 8.846); L6 (21.862, 8.846)-(21.862, 5.8); L7 (21.862, 5.8)-(20.361, 5.8); L8 (20.361, 5.8)-(20.361, 8.846); L9 (21.7, 9.041)-(20.201, 9.041); L10 (20.201, 9.041)-(20.201, 12.141); L11 (20.201, 12.141)-(21.7, 12.141); L12 (21.7, 12.141)-(21.7, 9.041); L13 (24.606, 7.397)-(24.606, 7.397) reference; L14 (24.631, 9.793)-(26.431, 9.793); L15 (26.431, 9.793)-(26.431, 6.597); L16 (26.431, 6.597)-(24.631, 6.597); L17 (24.631, 6.597)-(24.631, 9.793); L18 (12.95, 30)-(31.6, 30) reference; L19 (19.275, 8.028)-(19.275, 6.327); L20 (19.275, 6.327)-(15.982, 6.327); L21 (15.982, 6.327)-(15.982, 8.028); L22 (15.982, 8.028)-(19.275, 8.028); L23 (20.101, 12.241)-(20.101, 8.941); L24 (20.101, 8.941)-(21.8, 8.941); L25 (21.8, 8.941)-(21.8, 12.241); L26 (21.8, 12.241)-(20.101, 12.241); L27 (20.261, 8.946)-(21.962, 8.946); L28 (21.962, 8.946)-(21.962, 5.7); L29 (21.962, 5.7)-(20.261, 5.7); L30 (20.261, 5.7)-(20.261, 8.946); L31 (24.531, 9.893)-(26.531, 9.893); L32 (26.531, 9.893)-(26.531, 6.497); L33 (26.531, 6.497)-(24.531, 6.497); L34 (24.531, 6.497)-(24.531, 9.893); 5 further points; 1 other entity
  constraints: 64 end point, 24 perpendicular, 13 other
  dimensions: "d239" = 3.09352 distance of L3.end L1.start; "d240" = 1.50092 distance of L2.end L3.end; "d241" = 3.1 distance of L9.end L10.end; "d242" = 1.49926 distance of L10.end L11.end; "d243" = 3.046 distance of L5.end L6.end; "d244" = 1.50092 distance of L6.end L7.end; "d245" = 1.8 distance of L14.start L14.end; "d246" = 3.19582 distance of L16.end L14.start; "d247" = 22.0716 distance from line of L18 L3.end; "d248" = 17.8589 distance from line of L18 L10.end; "d249" = 21.15399 distance from line of L18 L5.end; "d250" = 20.20726 distance from line of L18 L14.end; "d251" = 0.1 distance between parallel lines of L4 L22; "d252" = 0.1 distance between parallel lines of L10 L23; "d253" = 0.1 distance between parallel lines of L8 L30; "d254" = 0.1 distance between parallel lines of L17 L34
extrude "Extrusión24" cut sketch "Boceto33" distance "d154" = 0.35; taper "d155" = 0 deg
sketch "Boceto34"
  geometry: L1 (16.301, 12.927)-(16.301, 27.369); L2 (16.301, 27.369)-(29.634, 27.369); L3 (29.634, 27.369)-(29.634, 12.927); L4 (29.634, 12.927)-(16.301, 12.927); L5 (12.95, 30)-(31.6, 30) reference; L6 (16.001, 27.669)-(16.001, 12.627); L7 (16.001, 12.627)-(29.934, 12.627); L8 (29.934, 12.627)-(29.934, 27.669); L9 (29.934, 27.669)-(16.001, 27.669)
  constraints: 16 end point, 4 perpendicular, 3 other
  dimensions: "d236" = 14.4418 distance of L1.start L1.end; "d237" = 13.33287 distance of L3.end L1.start; "d238" = 2.63113 distance between parallel lines of L5 L2; "d255" = 0.3 distance between parallel lines of L1 L6
extrude "Extrusión25" cut sketch "Boceto34" distance "d157" = 0.47; taper "d158" = 0 deg
sketch "Boceto37"
  geometry: 1 further point
sketch "Boceto38"
  geometry: L1 (-13.6, -11)-(-13.6, -7.274); L2 (-13.6, -7.274)-(-15.1, -7.274); L3 (-15.1, -7.274)-(-15.1, -11); L4 (-15.1, -11)-(-13.6, -11); L5 (-13.608, 13.5)-(-13.608, 16); L6 (-13.608, 13.5)-(-15.225, 13.5); L7 (-15.225, 13.5)-(-15.225, 16); L8 (-15.225, 16)-(-13.608, 16); L9 (16.05, 17.5)-(-15.3, 17.5) reference; L10 (13.609, 16)-(15.225, 16); L11 (13.609, 13.5)-(13.609, 16); L12 (13.609, 13.5)-(15.225, 13.5); L13 (13.609, -11)-(13.609, -8.25); L14 (13.609, -8.25)-(15.225, -8.25); L15 (15.225, -8.25)-(15.225, -11); L16 (13.609, -11)-(15.225, -11); L17 (-16.3, 16.5)-(-16.3, -14.5) reference; L18 (14.15, 0.1)-(14.85, 0.1) reference; L19 (13.484, 1.375)-(13.484, 3.875); L20 (13.484, 3.875)-(15.1, 3.875); L21 (13.484, 1.375)-(15.1, 1.375); L22 (15.1, 1.375)-(15.1, 3.875); L23 (-13.483, 1.375)-(-15.1, 1.375); L24 (-13.483, 3.875)-(-15.1, 3.875); L25 (-13.483, 3.875)-(-13.483, 1.375); L26 (-15.1, 3.875)-(-15.1, 1.375); 19 further points; 3 other entities
  constraints: 46 end point, 6 perpendicular, 5 horizontal, 4 vertical, 2 midpoint, 10 other
  dimensions: "d263" = 1.617 distance of L5.start L6.end; "d264" = 2.5 distance of L6.end L7.end; "d268" = 3.72581 distance of L1.start L1.end; "d269" = 1.5 distance of L1.end L2.end; "d276" = 2.5 distance of L11.start L10.start; "d277" = 1.616 distance of L11.start L12.end; "d278" = 1.5 distance between parallel lines of L9 L10; "d279" = 1.5 distance between parallel lines of L9 L8; "d281" = 24.77419 distance between parallel lines of L9 L2; "d287" = 2.75 distance of L13.start L13.end; "d288" = 1.616 distance of L13.end L14.end; "d289" = 25.75 distance between parallel lines of L9 L14; "d290" = 1.2 distance between parallel lines of L17 L3; "d292" = 2.5 distance of L19.start L19.end; "d293" = 1.616 distance of L19.end L20.end; "d295" = 9.625 distance from line of point (14.292, 3.875) L12; "d296" = 1.617 distance of L24.start L24.end; "d297" = 2.5 distance of L24.start L23.start; "d299" = 9.625 distance between parallel lines of L24 L6
extrude "Extrusión28" join sketch "Boceto38" distance "d176" = 1.4; taper "d177" = 0 deg
sketch "Boceto39"
  geometry: 1 further point
sketch "Boceto40"
  geometry: L1 (-1.911, 9.317)-(-2.096, 9.265); L2 (-2.096, 9.265)-(-2.225, 9.147); L3 (-2.225, 9.147)-(-2.293, 8.968); L4 (-2.293, 8.968)-(-2.382, 8.732); L5 (-2.382, 8.732)-(-2.282, 8.439); L6 (-2.282, 8.439)-(-2.066, 8.307); L7 (-2.066, 8.307)-(-2.005, 8.268); L8 (-2.005, 8.268)-(-2.005, 7.87); L9 (-2.005, 7.87)-(-2.005, 7.473); L10 (-2.005, 7.473)-(-2.341, 7.464); L11 (-2.341, 7.464)-(-2.652, 7.457); L12 (-2.652, 7.457)-(-2.682, 7.453); L13 (-2.682, 7.453)-(-2.774, 7.41); L14 (-2.774, 7.41)-(-3.058, 7.282); L15 (-3.058, 7.282)-(-3.131, 7.119); L16 (-3.131, 7.119)-(-3.131, 6.633); L17 (-3.131, 6.633)-(-3.131, 6.342); L18 (-3.131, 6.342)-(-3.533, 6.342); L19 (-3.533, 6.342)-(-3.933, 6.342); L20 (-3.933, 6.342)-(-3.987, 6.421); L21 (-3.987, 6.421)-(-4.233, 6.778); L22 (-4.233, 6.778)-(-4.78, 6.724); L23 (-4.78, 6.724)-(-4.958, 6.326); L24 (-4.958, 6.326)-(-5.016, 6.201); L25 (-5.016, 6.201)-(-5.012, 6.006); L26 (-5.012, 6.006)-(-4.951, 5.876); L27 (-4.951, 5.876)-(-4.853, 5.667); L28 (-4.853, 5.667)-(-4.673, 5.552); L29 (-4.673, 5.552)-(-4.444, 5.552); L30 (-4.444, 5.552)-(-4.342, 5.552); L31 (-4.342, 5.552)-(-4.292, 5.561); L32 (-4.292, 5.561)-(-4.217, 5.595); L33 (-4.217, 5.595)-(-4.121, 5.642); L34 (-4.121, 5.642)-(-3.979, 5.769); L35 (-3.979, 5.769)-(-3.96, 5.828); L36 (-3.96, 5.828)-(-3.951, 5.858); L37 (-3.951, 5.858)-(-3.92, 5.86); L38 (-3.92, 5.86)-(-3.54, 5.86); L39 (-3.54, 5.86)-(-3.131, 5.86); L40 (-3.131, 5.86)-(-3.131, 5.217); L41 (-3.131, 5.217)-(-3.131, 4.573); L42 (-3.131, 4.573)-(-3.531, 4.573); L43 (-3.531, 4.573)-(-3.929, 4.573); L44 (-3.929, 4.573)-(-3.999, 4.668); L45 (-3.999, 4.668)-(-4.053, 4.738); L46 (-4.053, 4.738)-(-4.101, 4.777); L47 (-4.101, 4.777)-(-4.192, 4.824); L48 (-4.192, 4.824)-(-4.303, 4.879); L49 (-4.303, 4.879)-(-4.33, 4.886); L50 (-4.33, 4.886)-(-4.451, 4.884); L51 (-4.451, 4.884)-(-4.614, 4.882); L52 (-4.614, 4.882)-(-4.726, 4.836); L53 (-4.726, 4.836)-(-4.837, 4.725); L54 (-4.837, 4.725)-(-4.951, 4.611); L55 (-4.951, 4.611)-(-4.996, 4.502); L56 (-4.996, 4.502)-(-4.996, 4.332); L57 (-4.996, 4.332)-(-4.996, 4.1); L58 (-4.996, 4.1)-(-4.896, 3.939); L59 (-4.896, 3.939)-(-4.69, 3.837); L60 (-4.69, 3.837)-(-4.533, 3.761); L61 (-4.533, 3.761)-(-4.371, 3.757); L62 (-4.371, 3.757)-(-4.217, 3.827); L63 (-4.217, 3.827)-(-4.115, 3.873); L64 (-4.115, 3.873)-(-3.981, 3.995)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; 279 further points
  constraints: 288 end point, 402 other
extrude "Extrusión29" cut sketch "Boceto40" distance "d178" = 0.2; taper "d179" = 0 deg
sketch "Boceto41"
  geometry: L1 (32.35, -1)-(32.35, -31.9) reference; L2 (17.675, -31.85)-(14.175, -31.85); L3 (14.175, -31.85)-(15.925, -33.25); L4 (17.675, -31.85)-(15.925, -33.25); 6 further points; 1 other entity
  constraints: 6 end point, 1 midpoint, 1 other
  dimensions: "d184" = 3.5 distance of L2.start L2.end; "d185" = 0.8 dimension on L3.end; "d186" = 1.4 distance of L3.end point (15.925, -31.85); "d187" = 16.425 distance from line of L1 L3.end
extrude "Extrusión30" cut sketch "Boceto41" distance "d188" = 0.1; taper "d189" = 0 deg
sketch "Boceto42"
  geometry: L1 (2.45, -2.146)-(2.45, 27.604) reference; L2 (2.45, 27.854)-(0, 27.854) reference; C1 r 0.825 at (0.85, 17.561); 1 further point
  constraints: 1 centre point
  dimensions: "d219" = 1.6 distance from line of L1 C1.centre; "d230" = 10.29294 distance from line of L2 C1.centre
extrude "Extrusión31" cut sketch "Boceto42" distance "d190" = 2.75; taper "d191" = 0 deg
sketch "Boceto43"
  geometry: L1 (32.35, -1)-(32.35, -32) reference; L2 (-0.25, -17.9)-(-0.25, -0.25) reference; L3 (16.1, 0)-(28.1, 0) reference; L4 (29.35, -1)-(2.75, -1); L5 (30.35, -30.35)-(30.35, -2); L6 (3.75, -31.35)-(1.75, -29.35); L7 (29.35, -31.35)-(3.75, -31.35); L8 (1.75, -29.35)-(1.75, -2); L9 (-0.25, -30)-(-0.25, -0.25) reference; L10 (0, 0)-(31.35, 0) reference; A1 r 1 centre (29.35, -30.35) between (29.35, -31.35) and (30.35, -30.35); A2 r 1 centre (29.35, -2) between (30.35, -2) and (29.35, -1); A3 r 1 centre (2.75, -2) between (2.75, -1) and (1.75, -2); 5 further points; 1 other entity
  constraints: 10 end point, 6 point on circle, 6 tangent, 3 centre point, 2 equal radius, 1 vertical, 1 other
  dimensions: "d200" = 1 radius of A1; "d300" = 2 distance between parallel lines of L9 L8; "d301" = 2.7 dimension on L7; "d302" = 2 distance between parallel lines of L1 L5; "d303" = 1 distance between parallel lines of L10 L4; "d305" = 2 horizontal distance of L6.end L6.start; "d306" = 2 horizontal distance of L6.end L6.start
extrude "Extrusión32" cut sketch "Boceto43" distance "d201" = 0.15; taper "d202" = 0 deg
feature "dspico 1-2"
feature "R0402_4:2"
feature "R0402_6:2"
feature "COMPOUND_(1)_8:7"
feature "COMPOUND_(1)_8:8"
feature "COMPOUND_(1)_8:9"
feature "COMPOUND_(1)_8:10"
feature "COMPOUND_(1)_8:11"
feature "COMPOUND_(1)_8:12"
feature "COMPOUND_(1)_15:52"
feature "COMPOUND_(1)_15:53"
feature "COMPOUND_(1)_15:54"
feature "COMPOUND_(1)_15:55"
feature "COMPOUND_(1)_15:56"
feature "COMPOUND_(1)_15:57"
feature "COMPOUND_(1)_15:58"
feature "COMPOUND_(1)_15:59"
feature "COMPOUND_(1)_15:60"
feature "COMPOUND_(1)_15:61"
feature "COMPOUND_(1)_15:62"
feature "COMPOUND_(1)_15:63"
feature "COMPOUND_(1)_15:64"
feature "COMPOUND_(1)_15:65"
feature "COMPOUND_(1)_15:66"
feature "COMPOUND_(1)_15:67"
feature "COMPOUND_(1)_15:68"
feature "COMPOUND_(1)_15:69"
feature "COMPOUND_(1)_15:70"
feature "COMPOUND_(1)_15:71"
feature "COMPOUND_(1)_15:72"
feature "COMPOUND_(1)_15:73"
feature "COMPOUND_(1)_15:74"
feature "COMPOUND_(1)_15:75"
feature "COMPOUND_(1)_15:76"
feature "COMPOUND_(1)_15:77"
feature "COMPOUND_(1)_15:78"
feature "COMPOUND_(1)_15:79"
feature "COMPOUND_(1)_15:80"
feature "COMPOUND_(1)_15:81"
feature "COMPOUND_(1)_15:82"
feature "COMPOUND_(1)_15:83"
feature "COMPOUND_(1)_15:84"
feature "COMPOUND_(1)_15:85"
feature "R0402_22:2"
feature "R0402_24:2"
feature "COMPOUND_(1)_15:86"
feature "COMPOUND_(1)_15:87"
feature "COMPOUND_(1)_15:88"
feature "COMPOUND_(1)_15:89"
feature "COMPOUND_(1)_15:90"
feature "COMPOUND_(1)_15:91"
feature "COMPOUND_(1)_15:92"
feature "COMPOUND_(1)_15:93"
feature "COMPOUND_(1)_15:94"
feature "COMPOUND_(1)_15:95"
feature "COMPOUND_(1)_15:96"
feature "COMPOUND_(1)_15:97"
feature "COMPOUND_(1)_15:98"
feature "COMPOUND_(1)_15:99"
feature "COMPOUND_(1)_15:100"
feature "COMPOUND_(1)_15:101"
feature "COMPOUND_(1)_15:102"
feature "ap2112k-3_3trg1_28:2"
feature "R0402_30:2"
feature "CAPC1005X56N_EIA_0402_32:2"
feature "CAPC1005X56N_EIA_0402_34:2"
feature "CAPC1005X56N_EIA_0402_36:2"
feature "CAPC1005X56N_EIA_0402_38:2"
feature "CAPC1005X56N_EIA_0402_40:2"
feature "CAPC1005X56N_EIA_0402_42:2"
feature "R0402_44:2"
feature "R0402_46:2"
feature "R0402_48:2"
feature "CAPC1005X56N_EIA_0402_50:2"
feature "CAPC1005X56N_EIA_0402_52:2"
feature "CAPC1005X56N_EIA_0402_54:2"
feature "CAPC1005X56N_EIA_0402_56:2"
feature "CAPC1005X56N_EIA_0402_58:2"
feature "CAPC1005X56N_EIA_0402_60:2"
feature "CAPC1005X56N_EIA_0402_62:2"
feature "CAPC1005X56N_EIA_0402_64:2"
feature "CAPC1005X56N_EIA_0402_66:2"
feature "COMPOUND_(1)_68:6"
feature "COMPOUND_(1)_68:7"
feature "COMPOUND_(1)_68:8"
feature "COMPOUND_(1)_68:9"
feature "COMPOUND_(1)_68:10"
feature "COMPOUND_(1)_73:3"
feature "COMPOUND_(1)_73:4"
feature "6532542400_78:1"
feature "6532542400_78:2"
feature "6532542400_78:3"
feature "6532542400_78:4"
feature "6532542400_78:5"
feature "6532542400_78:6"
feature "6532542400_78:7"
feature "6532542400_78:8"
feature "6532542400_78:9"
feature "6532542400_78:10"
feature "6532542400_78:11"
feature "6532542800_80:1"
feature "6532542800_80:2"
feature "6532542800_80:3"
feature "6532542800_80:4"
feature "6532542800_80:5"
feature "6532542800_80:6"
feature "6532542800_80:7"
feature "6532542800_80:8"
feature "6532542800_80:9"
feature "6532542800_80:10"
feature "6532542800_80:11"
feature "6532542800_80:12"
feature "6532542800_80:13"
feature "6532542800_80:14"
feature "6532542800_80:15"
feature "6532542800_80:16"
feature "6532542800_80:17"
feature "6532542800_80:18"
feature "6532542800_80:19"
feature "6532542800_80:20"
feature "6532542800_80:21"
feature "6532542800_80:22"
feature "6532542800_80:23"
feature "6532542800_80:24"
feature "6532542800_80:25"
feature "6532542800_80:26"
feature "6532542800_80:27"
feature "6532542800_80:28"
feature "6532542800_80:29"
feature "6532542800_80:30"
feature "6532542800_80:31"
feature "6532542800_80:32"
feature "6532542800_80:33"
feature "6532542800_80:34"
feature "6532542800_80:35"
feature "6532542800_80:36"
feature "6532542800_80:37"
feature "6532542800_80:38"
feature "6532542800_80:39"
feature "6532542800_80:40"
feature "6532542800_80:41"
feature "6532542800_80:42"
feature "6532542800_80:43"
feature "6532542800_80:44"
feature "6532542800_80:45"
feature "6532542800_80:46"
feature "6532542800_80:47"
feature "6532542800_80:48"
feature "6532542800_80:49"
feature "6532542800_80:50"
feature "6532542800_80:51"
feature "6532542800_80:52"
feature "6532542800_80:53"
feature "6532542800_80:54"
feature "6532542800_80:55"
feature "6532542800_80:56"
feature "6532542800_80:57"
feature "6532542800_80:58"
feature "6532542800_80:59"
feature "6532542800_80:60"
feature "6532542800_80:61"
feature "6532542800_80:62"
feature "6532542800_80:63"
feature "6532542800_80:64"
feature "6532542800_80:65"
feature "6532542800_80:66"
feature "6532542800_80:67"
feature "R0402_82:2"
feature "COMPOUND_(1)_84:8"
feature "COMPOUND_(1)_84:9"
feature "COMPOUND_(1)_84:10"
feature "COMPOUND_(1)_84:11"
feature "COMPOUND_(1)_84:12"
feature "COMPOUND_(1)_84:13"
feature "COMPOUND_(1)_84:14"
feature "R0402_89:2"
feature "R0402_91:2"
feature "R0402_93:2"
feature "R0402_95:2"
feature "R0402_97:2"
feature "5033981892_99:2"
feature "Micro_SD_Card_102:2"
